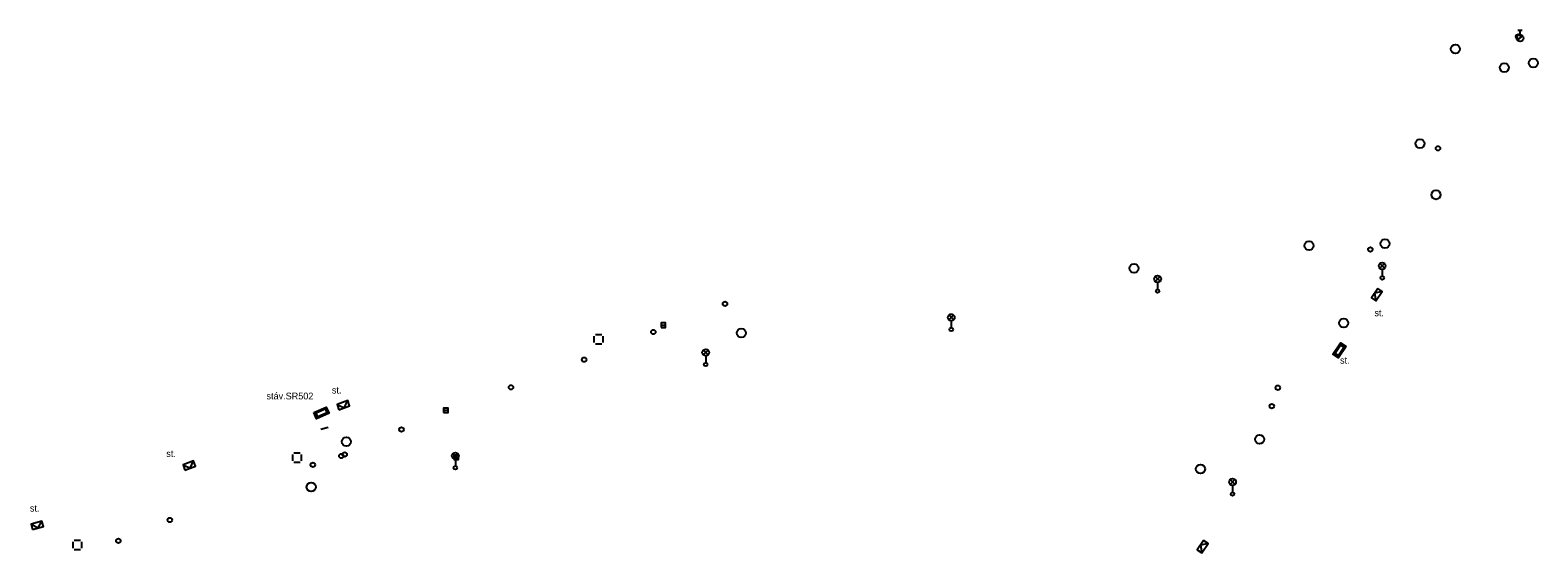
# Model space of a CAD drawing. Extents: x -762123 to -761396, y -1155152 to -1155021.
# Drawn here: x -761729.1 to -761562.4, y -1155152.3 to -1155094.5 of the extents above; entities that cross this region are included whole.
import ezdxf

# ---------------------------------------------------------------- set-up
doc = ezdxf.new("R2010")
doc.units = 0
for name, color, linetype in [('Vrstva 1', 7, 'Continuous'), ('Vrstva 11', 7, 'Continuous'), ('Vrstva 2', 7, 'Continuous'), ('Vrstva 9', 7, 'Continuous')]:
    doc.layers.add(name, color=color, linetype=linetype)

msp = doc.modelspace()

# ---------------------------------------------------------------- linework, layer by layer
at = {"layer": 'Vrstva 1'}
for points in [[(-761580.068, -1155123.053), (-761580.772, -1155124.087), (-761580.276, -1155124.424), (-761579.572, -1155123.391)], [(-761583.568, -1155129.482), (-761584.412, -1155130.722), (-761585.032, -1155130.3), (-761584.188, -1155129.06)], [(-761583.804, -1155129.563), (-761584.424, -1155130.472), (-761584.796, -1155130.219), (-761584.176, -1155129.31)], [(-761697.698, -1155136.765), (-761696.325, -1155136.162), (-761696.023, -1155136.848), (-761697.397, -1155137.452)], [(-761697.455, -1155136.822), (-761696.448, -1155136.379), (-761696.267, -1155136.791), (-761697.274, -1155137.234)], [(-761694.925, -1155136.459), (-761693.755, -1155136.021), (-761693.965, -1155135.459), (-761695.135, -1155135.897)], [(-761711.954, -1155143.132), (-761710.786, -1155142.688), (-761710.998, -1155142.127), (-761712.167, -1155142.571)], [(-761728.801, -1155149.702), (-761727.599, -1155149.358), (-761727.764, -1155148.781), (-761728.966, -1155149.125)], [(-761599.328, -1155150.913), (-761600.032, -1155151.947), (-761599.536, -1155152.284), (-761598.832, -1155151.251)]]:
    msp.add_lwpolyline(points, close=True, dxfattribs=at)
for points in [[(-761579.572, -1155123.391), (-761580.42, -1155123.57), (-761580.276, -1155124.424)], [(-761695.135, -1155135.897), (-761694.34, -1155136.24), (-761693.965, -1155135.459)], [(-761712.167, -1155142.571), (-761711.37, -1155142.91), (-761710.998, -1155142.127)], [(-761728.966, -1155149.125), (-761728.2, -1155149.53), (-761727.764, -1155148.781)], [(-761598.832, -1155151.251), (-761599.68, -1155151.43), (-761599.536, -1155152.284)]]:
    msp.add_lwpolyline(points, dxfattribs=at)
at = {"layer": 'Vrstva 11'}
msp.add_lwpolyline([(-761696.94, -1155138.61), (-761696.52, -1155138.49), (-761696.13, -1155138.38)], dxfattribs=at)
at = {"layer": 'Vrstva 9'}
for p, q in [((-761564.634, -1155095.601), (-761564.044, -1155095.138)), ((-761564.59, -1155094.495), (-761564.09, -1155094.495)), ((-761564.34, -1155094.995), (-761564.34, -1155094.495)), ((-761579.844, -1155120.828), (-761579.316, -1155120.3)), ((-761579.308, -1155120.825), (-761579.836, -1155120.296)), ((-761604.674, -1155122.268), (-761604.146, -1155121.74)), ((-761604.138, -1155122.265), (-761604.666, -1155121.736)), ((-761579.58, -1155120.94), (-761579.58, -1155121.69)), ((-761604.41, -1155122.38), (-761604.41, -1155123.13)), ((-761627.494, -1155126.518), (-761626.966, -1155125.99)), ((-761626.958, -1155126.515), (-761627.486, -1155125.986)), ((-761627.23, -1155126.63), (-761627.23, -1155127.38)), ((-761666.73, -1155128.34), (-761666.73, -1155129.04)), ((-761665.88, -1155128.19), (-761666.58, -1155128.19)), ((-761665.73, -1155129.04), (-761665.73, -1155128.34)), ((-761659.31, -1155127.12), (-761658.81, -1155127.12)), ((-761666.58, -1155129.19), (-761665.88, -1155129.19)), ((-761654.644, -1155130.398), (-761654.116, -1155129.87)), ((-761654.108, -1155130.395), (-761654.636, -1155129.866)), ((-761654.38, -1155130.51), (-761654.38, -1155131.26)), ((-761683.36, -1155136.52), (-761682.86, -1155136.52)), ((-761700.07, -1155141.41), (-761700.07, -1155142.11)), ((-761699.22, -1155141.26), (-761699.92, -1155141.26)), ((-761699.07, -1155142.11), (-761699.07, -1155141.41)), ((-761682.324, -1155141.818), (-761681.796, -1155141.29)), ((-761681.788, -1155141.815), (-761682.316, -1155141.286)), ((-761682.21, -1155141.73), (-761681.71, -1155141.73)), ((-761682.06, -1155141.93), (-761682.06, -1155142.68)), ((-761699.92, -1155142.26), (-761699.22, -1155142.26)), ((-761596.384, -1155144.718), (-761595.856, -1155144.19)), ((-761595.848, -1155144.715), (-761596.376, -1155144.186)), ((-761596.12, -1155144.83), (-761596.12, -1155145.58)), ((-761724.35, -1155151.06), (-761724.35, -1155151.76)), ((-761723.5, -1155150.91), (-761724.2, -1155150.91)), ((-761724.2, -1155151.91), (-761723.5, -1155151.91)), ((-761723.35, -1155151.76), (-761723.35, -1155151.06))]:
    msp.add_line(p, q, dxfattribs=at)
for points in [[(-761659.31, -1155127.371), (-761658.81, -1155127.371), (-761658.81, -1155126.87), (-761659.31, -1155126.87)], [(-761683.36, -1155136.771), (-761682.86, -1155136.771), (-761682.86, -1155136.27), (-761683.36, -1155136.27)], [(-761682.21, -1155141.981), (-761681.71, -1155141.981), (-761681.71, -1155141.48), (-761682.21, -1155141.48)]]:
    msp.add_lwpolyline(points, close=True, dxfattribs=at)
for centre, radius in [((-761564.54, -1155095.2), 0.25), ((-761564.34, -1155095.37), 0.375), ((-761571.48, -1155096.57), 0.5), ((-761566.08, -1155098.63), 0.5), ((-761562.87, -1155098.13), 0.5), ((-761575.4, -1155107.03), 0.5), ((-761573.41, -1155107.56), 0.25), ((-761573.63, -1155112.7), 0.5), ((-761587.67, -1155118.33), 0.5), ((-761580.89, -1155118.74), 0.25), ((-761579.27, -1155118.1), 0.5), ((-761607.02, -1155120.82), 0.5), ((-761579.58, -1155120.565), 0.375), ((-761604.41, -1155122.005), 0.375), ((-761579.58, -1155121.89), 0.2), ((-761604.41, -1155123.33), 0.2), ((-761652.24, -1155124.75), 0.25), ((-761627.23, -1155126.255), 0.375), ((-761583.83, -1155126.87), 0.5), ((-761660.17, -1155127.86), 0.25), ((-761650.44, -1155127.97), 0.5), ((-761627.23, -1155127.58), 0.2), ((-761654.38, -1155130.135), 0.375), ((-761667.81, -1155130.92), 0.25), ((-761654.38, -1155131.46), 0.2), ((-761675.91, -1155133.99), 0.25), ((-761591.11, -1155134.03), 0.25), ((-761591.79, -1155136.06), 0.25), ((-761688.02, -1155138.65), 0.25), ((-761694.11, -1155139.99), 0.5), ((-761593.14, -1155139.73), 0.5), ((-761694.67, -1155141.58), 0.25), ((-761694.29, -1155141.41), 0.25), ((-761682.06, -1155141.555), 0.375), ((-761697.81, -1155142.55), 0.25), ((-761682.06, -1155142.88), 0.2), ((-761599.67, -1155143.01), 0.5), ((-761698, -1155145.01), 0.5), ((-761596.12, -1155144.455), 0.375), ((-761596.12, -1155145.78), 0.2), ((-761713.63, -1155148.66), 0.25), ((-761719.32, -1155150.96), 0.25)]:
    msp.add_circle(centre, radius, dxfattribs=at)

# ---------------------------------------------------------------- texts
at = {"layer": 'Vrstva 2'}
for s, p in [('st.', (-761580.44, -1155126.12)), ('st.', (-761584.24, -1155131.37)), ('stáv.SR502', (-761702.94, -1155135.32)), ('st.', (-761695.71, -1155134.67)), ('st.', (-761714.02, -1155141.69)), ('st.', (-761729.1, -1155147.73))]:
    msp.add_text(s, height=0.75, dxfattribs=at).set_placement(p)

doc.saveas('drawing.dxf')
